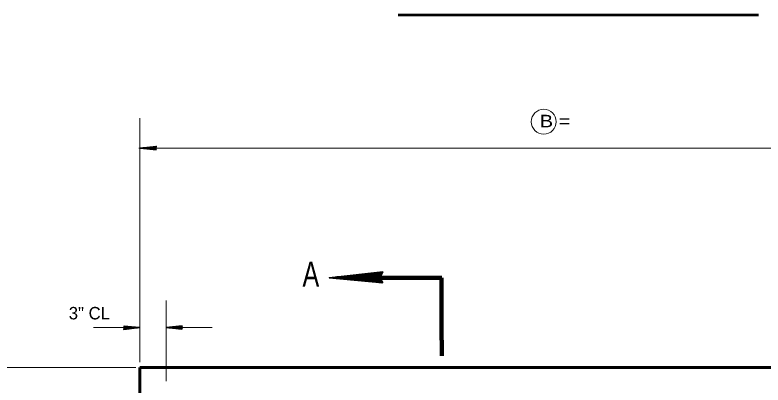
# Model space of a CAD drawing. Extents: x 4.49 to 7.69, y 0.28 to 2.27.
# Drawn here: x 4.7957 to 5.2955, y 1.004 to 1.2514 of the extents above; entities that cross this region are included whole.
import ezdxf

# ---------------------------------------------------------------- set-up
doc = ezdxf.new("R2010")
doc.units = 0
doc.header["$LTSCALE"] = 0.0033
doc.layers.add('1', color=7, linetype='Continuous', lineweight=35)

msp = doc.modelspace()

# ---------------------------------------------------------------- linework, layer by layer
at = {"layer": '1', "lineweight": 53}
msp.add_line((5.05175, 1.251417), (5.2925, 1.251417), dxfattribs=at)
at = {"layer": '1', "lineweight": 13}
for p, q in [((4.879083, 1.01925), (4.879083, 1.182417)), ((4.89675, 1.006667), (4.89675, 1.060583)), ((4.848083, 1.042417), (4.868917, 1.042417)), ((4.906667, 1.042417), (4.9275, 1.042417)), ((4.8765, 1.01575), (4.712417, 1.01575))]:
    msp.add_line(p, q, dxfattribs=at)
at = {"layer": '1'}
for p, q in [((4.890167, 1.162417), (4.879583, 1.162417)), ((4.889917, 1.161583), (4.882083, 1.162583)), ((4.889917, 1.161583), (4.882083, 1.162417)), ((4.889917, 1.161417), (4.882083, 1.162333)), ((4.889917, 1.161417), (4.882083, 1.162333)), ((4.889917, 1.1615), (4.882083, 1.162333)), ((4.889917, 1.1635), (4.882583, 1.162667)), ((4.889917, 1.163333), (4.882583, 1.162583)), ((4.889917, 1.16325), (4.882583, 1.162417)), ((4.89, 1.163083), (4.882667, 1.162333)), ((5.041417, 1.07575), (5.00575, 1.07575)), ((5.040667, 1.073), (5.014083, 1.076333)), ((5.040667, 1.073), (5.014083, 1.07575)), ((5.040667, 1.072333), (5.014083, 1.075583)), ((5.040667, 1.072333), (5.014083, 1.075583)), ((5.040667, 1.07275), (5.014083, 1.075583)), ((5.040667, 1.0795), (5.015917, 1.07675)), ((5.040667, 1.079), (5.015917, 1.076333)), ((5.040667, 1.078583), (5.015917, 1.07575)), ((5.040917, 1.078), (5.016, 1.075583)), ((4.868417, 1.042417), (4.879, 1.042417)), ((4.868583, 1.04175), (4.875917, 1.0425)), ((4.868667, 1.043417), (4.8765, 1.0425)), ((4.868667, 1.043417), (4.8765, 1.0425)), ((4.868667, 1.043333), (4.8765, 1.0425)), ((4.868667, 1.04325), (4.8765, 1.042417)), ((4.868667, 1.04325), (4.8765, 1.04225)), ((4.868667, 1.041583), (4.876, 1.042417)), ((4.868667, 1.0415), (4.876, 1.04225)), ((4.868667, 1.041333), (4.876, 1.042167)), ((4.907333, 1.042417), (4.89675, 1.042417)), ((4.907083, 1.041583), (4.89925, 1.042583)), ((4.907083, 1.041583), (4.89925, 1.042417)), ((4.907083, 1.041417), (4.89925, 1.042333)), ((4.907083, 1.041417), (4.89925, 1.042333)), ((4.907083, 1.0415), (4.89925, 1.042333)), ((4.907083, 1.0435), (4.89975, 1.042667)), ((4.907083, 1.043333), (4.89975, 1.042583)), ((4.907083, 1.04325), (4.89975, 1.042417)), ((4.907167, 1.043083), (4.899833, 1.042333))]:
    msp.add_line(p, q, dxfattribs=at)
at = {"layer": '1', "lineweight": 90}
for p, q in [((5.03925, 1.075667), (5.080917, 1.075667)), ((5.08075, 1.07575), (5.08075, 1.034083)), ((5.080917, 1.034), (5.080917, 1.0235))]:
    msp.add_line(p, q, dxfattribs=at)
at = {"layer": '1', "lineweight": 60}
for p, q in [((4.879083, 1.01575), (5.157083, 1.01575)), ((5.122333, 1.01575), (5.462417, 1.01575))]:
    msp.add_line(p, q, dxfattribs=at)
at = {"layer": '1', "lineweight": 13}
msp.add_lwpolyline([(4.878417, 1.162417), (5.18125, 1.162417), (5.46175, 1.162417)], dxfattribs=at)
at = {"layer": '1'}
for points in [[(4.890167, 1.161333), (4.879583, 1.162417), (4.890167, 1.163583), (4.889583, 1.162417)], [(4.889417, 1.162333), (4.88475, 1.16225), (4.88475, 1.162333), (4.885667, 1.162333), (4.889417, 1.16225), (4.886417, 1.162167), (4.889583, 1.162083), (4.887333, 1.162), (4.889583, 1.161917), (4.886083, 1.162167), (4.881417, 1.162333), (4.882333, 1.162583), (4.881083, 1.162583), (4.889417, 1.162583), (4.887, 1.16275), (4.889583, 1.16275), (4.88425, 1.162333), (4.889583, 1.163)], [(5.041417, 1.07225), (5.00575, 1.07575), (5.041417, 1.07975), (5.0395, 1.07575)], [(5.039, 1.075583), (5.023167, 1.07525), (5.023167, 1.075583), (5.026167, 1.075583), (5.039, 1.07525), (5.02875, 1.075), (5.0395, 1.074583), (5.03175, 1.0745), (5.0395, 1.074083), (5.027667, 1.075), (5.011833, 1.075583), (5.014917, 1.076333), (5.01075, 1.076333), (5.039, 1.076333), (5.030667, 1.076833), (5.0395, 1.076833), (5.0215, 1.075583), (5.0395, 1.077833)], [(4.868417, 1.0435), (4.879, 1.042417), (4.868417, 1.04125), (4.869, 1.042417)], [(4.869167, 1.0425), (4.873833, 1.042583), (4.873833, 1.0425), (4.872917, 1.0425), (4.869167, 1.042583), (4.872167, 1.042667), (4.869, 1.04275), (4.87125, 1.042833), (4.869, 1.042917), (4.8725, 1.042667), (4.877167, 1.0425), (4.87625, 1.04225), (4.8775, 1.04225), (4.869167, 1.04225), (4.871583, 1.042083), (4.869, 1.042083), (4.874333, 1.0425), (4.869, 1.041833)], [(4.907333, 1.041333), (4.89675, 1.042417), (4.907333, 1.043583), (4.90675, 1.042417)], [(4.906583, 1.042333), (4.901917, 1.04225), (4.901917, 1.042333), (4.902833, 1.042333), (4.906583, 1.04225), (4.903583, 1.042167), (4.90675, 1.042083), (4.9045, 1.042), (4.90675, 1.041917), (4.90325, 1.042167), (4.898583, 1.042333), (4.8995, 1.042583), (4.89825, 1.042583), (4.906583, 1.042583), (4.904167, 1.04275), (4.90675, 1.04275), (4.901417, 1.042333), (4.90675, 1.043)]]:
    msp.add_lwpolyline(points, close=True, dxfattribs=at)
for points in [[(4.889417, 1.162333), (4.889833, 1.161583), (4.889583, 1.161833), (4.889417, 1.162167), (4.889167, 1.162083), (4.889333, 1.16175), (4.8895, 1.1625), (4.889667, 1.163), (4.889917, 1.163417)], [(5.039, 1.075583), (5.04025, 1.073), (5.0395, 1.073833), (5.039, 1.075), (5.038, 1.074583), (5.038667, 1.0735), (5.039167, 1.076083), (5.03975, 1.077833), (5.040667, 1.079083)], [(4.869167, 1.0425), (4.86875, 1.04325), (4.869, 1.043), (4.869167, 1.042667), (4.869417, 1.04275), (4.86925, 1.043083), (4.869083, 1.042333), (4.868917, 1.041833), (4.868667, 1.041417)], [(4.906583, 1.042333), (4.907, 1.041583), (4.90675, 1.041833), (4.906583, 1.042167), (4.906333, 1.042083), (4.9065, 1.04175), (4.906667, 1.0425), (4.906833, 1.043), (4.907083, 1.043417)]]:
    msp.add_lwpolyline(points, dxfattribs=at)
at = {"layer": '1', "lineweight": 60}
msp.add_lwpolyline([(4.79575, 0.599083), (4.79575, 0.682417), (4.879083, 0.682417), (4.879083, 1.01575)], dxfattribs=at)
at = {"layer": '1', "lineweight": 13}
msp.add_circle((5.149, 1.180083), 0.008333, dxfattribs=at)

# ---------------------------------------------------------------- texts
at = {"layer": '1'}
for s, height, width, p in [('B =      ', 0.008334, 1.2, (5.146333, 1.176333)), ('A', 0.01667, 0.75, (4.987833, 1.069833))]:
    msp.add_text(s, height=height, dxfattribs=dict(at, width=width)).set_placement(p)
msp.add_text('3" CL', height=0.008334, dxfattribs=at).set_placement((4.831667, 1.047917))

doc.saveas('drawing.dxf')
